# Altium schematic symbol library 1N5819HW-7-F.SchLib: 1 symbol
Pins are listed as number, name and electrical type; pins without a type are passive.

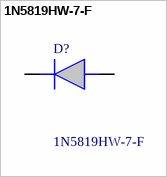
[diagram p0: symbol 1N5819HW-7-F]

## 1N5819HW-7-F
designator D?
Diode Schottky 1A 40V SOD123 Diodes Inc 1N5819HW-7-F, SMT Schottky Diode, 40V 1A, 2-Pin SOD-123; Manufacturer_Name: Diodes Incorporated; Geometry.Height: 1.45mm
footprint SOD3716X145N
pins: 1 K, 2 A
